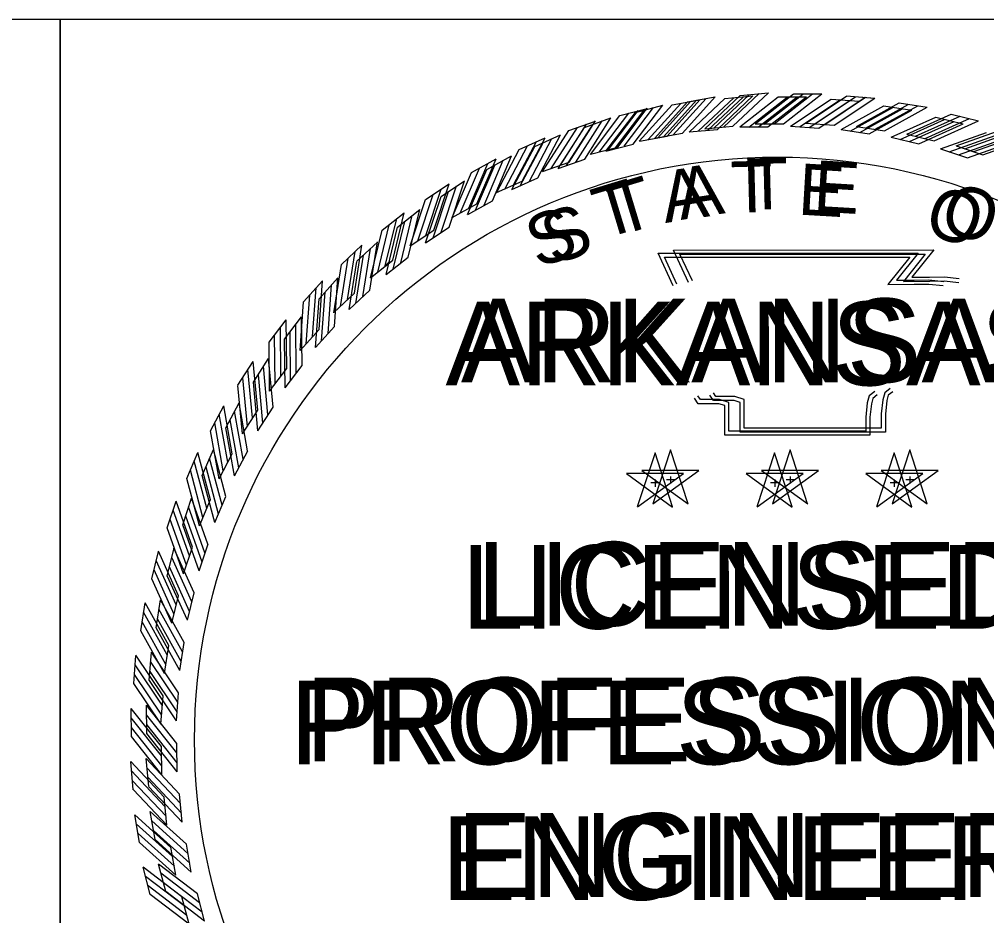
# Model space of a CAD drawing. Extents: x -2512 to 3792, y -435 to 2624.
# Drawn here: x 3002.5 to 3189.1, y 315.8 to 488.7 of the extents above; entities that cross this region are included whole.
import ezdxf

# ---------------------------------------------------------------- set-up
doc = ezdxf.new("R2010")
doc.units = 0
for name, color, linetype in [('1', 7, 'Continuous'), ('G-ANNO-NPLT', 7, 'Continuous'), ('R_No Plot', 7, 'Continuous'), ('STAMP', 7, 'Continuous'), ('STAMP_LKM', 7, 'Continuous')]:
    doc.layers.add(name, color=color, linetype=linetype)

msp = doc.modelspace()

# ---------------------------------------------------------------- linework, layer by layer
at = {"layer": '1'}
msp.add_line((3073.06, 441.09), (3073.99, 442.02), dxfattribs=at)
at = {"layer": 'G-ANNO-NPLT'}
msp.add_circle((3148.72, 349.66), 112.43, dxfattribs=at)
at = {"layer": 'R_No Plot'}
for points in [[(2730.1, 488.67), (3010.37, 488.67), (3010.37, 212.74), (2730.1, 212.74)], [(3010.37, 488.67), (3290.65, 488.67), (3290.65, 212.74), (3010.37, 212.74)]]:
    msp.add_lwpolyline(points, close=True, dxfattribs=at)
at = {"layer": 'STAMP'}
for p, q in [((3128.4, 472.17), (3133.75, 473.12)), ((3138.58, 473.39), (3144, 473.89)), ((3148.88, 473.69), (3154.32, 473.69)), ((3159.07, 473.28), (3164.5, 472.88)), ((3118.35, 470.12), (3123.61, 471.5)), ((3169.24, 471.96), (3174.62, 471.12)), ((3108.5, 467.24), (3113.63, 469.05)), ((3179.27, 469.81), (3184.56, 468.52)), ((3131.72, 466.94), (3137.15, 467.44)), ((3141.46, 467.9), (3146.91, 467.9)), ((3151.24, 468.05), (3156.68, 467.65)), ((3161.01, 467.4), (3166.4, 466.55)), ((3098.93, 463.56), (3103.89, 465.79)), ((3122.09, 465.18), (3127.46, 466.13)), ((3170.69, 465.94), (3175.99, 464.65)), ((3112.64, 462.63), (3117.91, 464.02)), ((3180.21, 463.68), (3185.39, 461.96)), ((3089.69, 459.1), (3094.45, 461.74)), ((3103.43, 459.31), (3108.57, 461.12)), ((3094.53, 455.24), (3099.51, 457.47)), ((3080.86, 453.9), (3085.38, 456.92)), ((3086, 450.44), (3090.77, 453.08)), ((3072.48, 447.98), (3076.74, 451.36)), ((3077.89, 444.96), (3082.43, 447.99)), ((3064.62, 441.39), (3068.59, 445.12)), ((3070.26, 438.83), (3074.53, 442.22)), ((3057.33, 434.18), (3060.98, 438.22)), ((3063.16, 432.09), (3067.14, 435.82)), ((3050.66, 426.39), (3053.96, 430.71)), ((3056.65, 424.79), (3060.3, 428.83)), ((3044.66, 418.07), (3047.59, 422.65)), ((3050.76, 416.97), (3054.07, 421.31)), ((3039.37, 409.29), (3041.91, 414.1)), ((3045.53, 408.7), (3048.47, 413.29)), ((3034.81, 400.1), (3036.95, 405.1)), ((3125.11, 405.04), (3121.7, 394.6)), ((3128.5, 394.61), (3125.11, 405.06)), ((3148.19, 405.04), (3144.78, 394.6)), ((3151.58, 394.61), (3148.19, 405.06)), ((3171.26, 405.04), (3167.86, 394.6)), ((3174.65, 394.61), (3171.27, 405.06)), ((3041.01, 400.02), (3043.56, 404.84)), ((3130.59, 401.06), (3119.61, 401.07)), ((3119.62, 401.06), (3128.5, 394.59)), ((3121.72, 394.61), (3130.61, 401.05)), ((3124.33, 399.3), (3125.96, 399.3)), ((3125.12, 399.89), (3125.12, 398.51)), ((3153.67, 401.06), (3142.69, 401.07)), ((3142.7, 401.06), (3151.58, 394.59)), ((3144.79, 394.61), (3153.69, 401.05)), ((3147.4, 399.3), (3149.04, 399.3)), ((3148.2, 399.89), (3148.2, 398.51)), ((3176.75, 401.06), (3165.77, 401.07)), ((3165.78, 401.06), (3174.66, 394.59)), ((3167.87, 394.61), (3176.76, 401.05)), ((3170.48, 399.3), (3172.11, 399.3)), ((3171.27, 399.89), (3171.27, 398.51)), ((3031.04, 390.56), (3032.76, 395.72)), ((3037.22, 390.99), (3039.36, 396.01)), ((3034.18, 381.69), (3035.91, 386.86)), ((3028.06, 380.75), (3029.35, 386.03)), ((3031.93, 372.16), (3033.22, 377.46)), ((3025.9, 370.72), (3026.75, 376.09)), ((3030.47, 362.48), (3031.32, 367.87)), ((3024.58, 360.55), (3024.98, 365.97)), ((3029.81, 352.72), (3030.21, 358.16)), ((3024.11, 350.3), (3024.06, 355.74)), ((3029.97, 342.93), (3029.92, 348.39)), ((3024.48, 340.05), (3023.98, 345.47)), ((3030.93, 333.19), (3030.43, 338.62)), ((3025.7, 329.87), (3024.75, 335.23)), ((3032.69, 323.56), (3031.74, 328.94)), ((3027.75, 319.82), (3026.37, 325.08)), ((3035.24, 314.12), (3033.85, 319.39))]:
    msp.add_line(p, q, dxfattribs=at)
for points in [[(3122.08, 465.17), (3128.39, 472.16)], [(3123.81, 465.46), (3130.12, 472.45)], [(3125.67, 465.83), (3131.97, 472.82)], [(3127.45, 466.13), (3133.76, 473.12)], [(3131.71, 466.93), (3138.57, 473.38)], [(3133.46, 467.08), (3140.32, 473.53)], [(3135.33, 467.29), (3142.2, 473.74)], [(3137.14, 467.44), (3144, 473.89)], [(3141.45, 467.9), (3148.87, 473.69)], [(3143.2, 467.88), (3150.63, 473.67)], [(3145.09, 467.92), (3152.52, 473.71)], [(3146.9, 467.9), (3154.33, 473.69)], [(3151.24, 468.05), (3159.07, 473.28)], [(3152.98, 467.9), (3160.81, 473.13)], [(3154.87, 467.81), (3162.7, 473.04)], [(3156.68, 467.66), (3164.5, 472.89)], [(3114.33, 463.05), (3120.04, 470.54)], [(3116.15, 463.57), (3121.86, 471.06)], [(3117.91, 464.02), (3123.61, 471.51)], [(3161, 467.39), (3169.24, 471.96)], [(3162.73, 467.1), (3170.96, 471.67)], [(3164.6, 466.85), (3172.84, 471.42)], [(3166.39, 466.55), (3174.62, 471.12)], [(3106.85, 460.54), (3111.92, 468.47)], [(3108.57, 461.13), (3113.64, 469.06)], [(3112.64, 462.62), (3118.34, 470.11)], [(3170.68, 465.93), (3179.26, 469.8)], [(3172.38, 465.5), (3180.96, 469.37)], [(3174.22, 465.1), (3182.81, 468.97)], [(3175.98, 464.65), (3184.56, 468.52)], [(3103.43, 459.3), (3108.5, 467.23)], [(3105.09, 459.87), (3110.15, 467.8)], [(3180.2, 463.68), (3189.08, 466.83)], [(3097.84, 456.75), (3102.24, 465.07)], [(3099.5, 457.47), (3103.9, 465.8)], [(3181.86, 463.11), (3190.73, 466.26)], [(3183.67, 462.55), (3192.54, 465.7)], [(3185.38, 461.96), (3194.25, 465.11)], [(3094.53, 455.23), (3098.93, 463.55)], [(3096.13, 455.93), (3100.53, 464.26)], [(3089.17, 452.22), (3092.86, 460.88)], [(3090.76, 453.08), (3094.46, 461.74)], [(3086, 450.44), (3089.69, 459.1)], [(3087.54, 451.27), (3091.23, 459.93)], [(3080.9, 447), (3083.87, 455.93)], [(3082.42, 447.99), (3085.39, 456.92)], [(3077.89, 444.96), (3080.85, 453.89)], [(3079.35, 445.91), (3082.32, 454.85)], [(3073.09, 441.11), (3075.31, 450.26)], [(3074.53, 442.22), (3076.74, 451.37)], [(3070.26, 438.82), (3072.48, 447.97)], [(3071.64, 439.9), (3073.86, 449.05)], [(3067.13, 435.82), (3068.59, 445.12)], [(3064.45, 433.27), (3065.91, 442.57)], [(3065.8, 434.59), (3067.26, 443.89)], [(3128.61, 437.28), (3125.71, 443.56), (3175.89, 443.59), (3171.7, 438.32), (3175.11, 438.36), (3177.95, 438.4), (3180.8, 438.09)], [(3129.33, 437.61), (3126.95, 442.76), (3174.24, 442.79), (3170.03, 437.5), (3175.12, 437.57), (3177.92, 437.6), (3180.71, 437.3)], [(3063.16, 432.08), (3064.62, 441.38)], [(3059.07, 427.5), (3059.75, 436.89)], [(3060.3, 428.83), (3060.98, 438.22)], [(3057.83, 426.07), (3058.51, 435.46)], [(3056.65, 424.78), (3057.33, 434.17)], [(3052.95, 419.87), (3052.85, 429.29)], [(3054.06, 421.3), (3053.96, 430.72)], [(3051.83, 418.35), (3051.74, 427.76)], [(3050.76, 416.96), (3050.66, 426.38)], [(3048.47, 413.29), (3047.59, 422.66)], [(3047.47, 411.77), (3046.6, 421.14)], [(3045.53, 408.69), (3044.66, 418.06)], [(3046.49, 410.15), (3045.62, 419.53)], [(3167.98, 416.25), (3167.13, 415.55), (3166.84, 414.51), (3166.56, 411.91), (3166.56, 408.44), (3138.55, 408.44), (3138.55, 413.12), (3138.55, 414.16), (3137.41, 414.51), (3133.43, 414.51), (3132.72, 415.59)], [(3167.48, 416.86), (3166.43, 416.01), (3166.06, 414.66), (3165.76, 411.95), (3165.76, 409.24), (3139.34, 409.24), (3139.34, 413.12), (3139.34, 414.75), (3137.53, 415.31), (3133.86, 415.31), (3133.38, 416.03)], [(3042.69, 403.24), (3041.05, 412.51)], [(3043.55, 404.83), (3041.91, 414.1)], [(3041.84, 401.55), (3040.2, 410.82)], [(3041.01, 400.01), (3039.37, 409.28)], [(3039.36, 396), (3036.95, 405.1)], [(3038.63, 394.34), (3036.22, 403.44)], [(3037.92, 392.59), (3035.52, 401.69)], [(3037.22, 390.98), (3034.82, 400.09)], [(3035.9, 386.86), (3032.75, 395.73)], [(3035.31, 385.14), (3032.17, 394.01)], [(3034.76, 383.34), (3031.61, 392.21)], [(3034.19, 381.68), (3031.04, 390.55)], [(3033.21, 377.46), (3029.34, 386.04)], [(3032.77, 375.7), (3028.9, 384.28)], [(3031.93, 372.16), (3028.06, 380.74)], [(3032.36, 373.85), (3028.49, 382.44)], [(3031.31, 367.87), (3026.75, 376.1)], [(3031.01, 366.08), (3026.45, 374.31)], [(3030.76, 364.2), (3026.2, 372.44)], [(3030.47, 362.48), (3025.91, 370.71)], [(3030.21, 358.15), (3024.98, 365.98)], [(3030.06, 356.35), (3024.83, 364.17)], [(3029.96, 354.46), (3024.73, 362.29)], [(3029.82, 352.71), (3024.59, 360.54)], [(3029.91, 348.38), (3024.05, 355.75)], [(3029.91, 346.57), (3024.05, 353.94)], [(3029.97, 344.68), (3024.11, 352.05)], [(3029.97, 342.93), (3024.11, 350.3)], [(3030.42, 338.62), (3023.98, 345.48)], [(3030.57, 336.81), (3024.13, 343.67)], [(3030.79, 334.93), (3024.34, 341.79)], [(3030.93, 333.19), (3024.49, 340.05)], [(3031.74, 328.93), (3024.75, 335.23)], [(3032.04, 327.14), (3025.05, 333.45)], [(3032.41, 325.29), (3025.41, 331.59)], [(3032.69, 323.56), (3025.7, 329.86)], [(3033.85, 319.38), (3026.36, 325.09)], [(3034.29, 317.63), (3026.81, 323.33)], [(3034.81, 315.81), (3027.33, 321.51)], [(3035.24, 314.11), (3027.76, 319.82)]]:
    msp.add_lwpolyline(points, dxfattribs=at)
at = {"layer": 'STAMP_LKM'}
for p, q in [((3141.56, 473.98), (3146.98, 474.48)), ((3151.86, 474.28), (3157.3, 474.28)), ((3121.33, 470.71), (3126.59, 472.1)), ((3131.37, 472.76), (3136.73, 473.71)), ((3162.05, 473.88), (3167.47, 473.48)), ((3162.05, 473.88), (3167.48, 473.48)), ((3172.22, 472.56), (3177.6, 471.71)), ((3182.25, 470.4), (3187.54, 469.11)), ((3111.48, 467.83), (3116.61, 469.65)), ((3144.44, 468.5), (3149.89, 468.5)), ((3154.22, 468.65), (3159.66, 468.25)), ((3154.22, 468.65), (3159.66, 468.25)), ((3125.07, 465.77), (3130.44, 466.72)), ((3134.7, 467.53), (3140.13, 468.04)), ((3163.99, 467.99), (3169.37, 467.14)), ((3173.67, 466.53), (3178.96, 465.24)), ((3101.91, 464.16), (3106.87, 466.39)), ((3115.62, 463.22), (3120.89, 464.61)), ((3183.19, 464.28), (3188.36, 462.55)), ((3092.67, 459.7), (3097.43, 462.33)), ((3106.41, 459.9), (3111.55, 461.72)), ((3083.83, 454.49), (3088.36, 457.51)), ((3097.51, 455.83), (3102.48, 458.07)), ((3088.98, 451.04), (3093.75, 453.68)), ((3075.46, 448.58), (3079.72, 451.96)), ((3080.87, 445.56), (3085.4, 448.58)), ((3067.6, 441.99), (3071.57, 445.71)), ((3073.24, 439.43), (3077.51, 442.82)), ((3060.31, 434.77), (3063.96, 438.81)), ((3066.14, 432.69), (3070.12, 436.42)), ((3053.64, 426.98), (3056.94, 431.31)), ((3059.63, 425.38), (3063.28, 429.43)), ((3047.64, 418.66), (3050.57, 423.25)), ((3053.74, 417.57), (3057.04, 421.9)), ((3042.34, 409.88), (3044.89, 414.69)), ((3048.51, 409.29), (3051.45, 413.88)), ((3037.79, 400.69), (3039.93, 405.69)), ((3043.99, 400.61), (3046.54, 405.43)), ((3128.08, 405.64), (3124.68, 395.19)), ((3131.48, 395.2), (3128.09, 405.65)), ((3151.16, 405.64), (3147.76, 395.19)), ((3154.55, 395.2), (3151.17, 405.65)), ((3174.24, 405.64), (3170.84, 395.19)), ((3177.63, 395.2), (3174.25, 405.65)), ((3133.57, 401.65), (3122.59, 401.66)), ((3122.6, 401.65), (3131.48, 395.19)), ((3124.69, 395.2), (3133.59, 401.65)), ((3156.65, 401.65), (3145.67, 401.66)), ((3145.68, 401.65), (3154.56, 395.19)), ((3147.77, 395.2), (3156.66, 401.65)), ((3179.73, 401.65), (3168.74, 401.66)), ((3168.75, 401.65), (3177.63, 395.19)), ((3170.85, 395.2), (3179.74, 401.65)), ((3127.3, 399.9), (3128.94, 399.9)), ((3128.1, 400.48), (3128.1, 399.1)), ((3150.38, 399.9), (3152.01, 399.9)), ((3151.17, 400.48), (3151.17, 399.1)), ((3173.46, 399.9), (3175.09, 399.9)), ((3174.25, 400.48), (3174.25, 399.1)), ((3034.02, 391.16), (3035.73, 396.32)), ((3040.2, 391.59), (3042.34, 396.6)), ((3031.04, 381.34), (3032.33, 386.63)), ((3037.16, 382.28), (3038.89, 387.46)), ((3034.91, 372.76), (3036.2, 378.06)), ((3028.88, 371.31), (3029.73, 376.69)), ((3033.45, 363.08), (3034.3, 368.47)), ((3027.56, 361.14), (3027.96, 366.57)), ((3032.79, 353.31), (3033.19, 358.75)), ((3027.09, 350.9), (3027.04, 356.34)), ((3032.94, 343.53), (3032.89, 348.98)), ((3027.46, 340.65), (3026.96, 346.07)), ((3033.9, 333.79), (3033.4, 339.22)), ((3028.67, 330.47), (3027.73, 335.82)), ((3035.67, 324.16), (3034.72, 329.53)), ((3030.73, 320.42), (3029.34, 325.68)), ((3038.22, 314.71), (3036.83, 319.98))]:
    msp.add_line(p, q, dxfattribs=at)
for points in [[(3134.69, 467.53), (3141.55, 473.98)], [(3136.43, 467.67), (3143.3, 474.12)], [(3138.31, 467.89), (3145.17, 474.33)], [(3140.12, 468.04), (3146.98, 474.48)], [(3144.43, 468.49), (3151.85, 474.28)], [(3146.18, 468.47), (3153.6, 474.26)], [(3148.07, 468.52), (3155.49, 474.31)], [(3149.88, 468.5), (3157.31, 474.29)], [(3120.88, 464.61), (3126.59, 472.1)], [(3125.06, 465.77), (3131.37, 472.76)], [(3126.79, 466.06), (3133.09, 473.05)], [(3128.64, 466.42), (3134.95, 473.42)], [(3130.43, 466.72), (3136.74, 473.71)], [(3154.21, 468.64), (3162.04, 473.87)], [(3154.21, 468.64), (3162.04, 473.87)], [(3155.96, 468.5), (3163.79, 473.73)], [(3155.96, 468.5), (3163.79, 473.73)], [(3157.85, 468.4), (3165.67, 473.63)], [(3157.85, 468.4), (3165.68, 473.63)], [(3159.65, 468.25), (3167.48, 473.48)], [(3159.65, 468.25), (3167.48, 473.48)], [(3163.98, 467.99), (3172.21, 472.55)], [(3165.71, 467.7), (3173.94, 472.26)], [(3115.61, 463.22), (3121.32, 470.7)], [(3117.31, 463.65), (3123.02, 471.13)], [(3119.13, 464.17), (3124.83, 471.66)], [(3167.58, 467.45), (3175.81, 472.01)], [(3169.37, 467.15), (3177.6, 471.71)], [(3173.66, 466.53), (3182.24, 470.4)], [(3108.06, 460.46), (3113.13, 468.4)], [(3109.83, 461.13), (3114.9, 469.07)], [(3111.55, 461.72), (3116.61, 469.65)], [(3175.36, 466.1), (3183.94, 469.97)], [(3177.2, 465.69), (3185.78, 469.56)], [(3178.96, 465.25), (3187.54, 469.12)], [(3106.41, 459.89), (3111.48, 467.83)], [(3183.18, 464.27), (3192.05, 467.42)], [(3184.84, 463.71), (3193.71, 466.85)], [(3099.11, 456.53), (3103.51, 464.85)], [(3100.82, 457.34), (3105.21, 465.66)], [(3102.48, 458.07), (3106.87, 466.39)], [(3186.64, 463.15), (3195.52, 466.3)], [(3188.36, 462.56), (3197.23, 465.71)], [(3097.51, 455.82), (3101.9, 464.15)], [(3092.15, 452.82), (3095.84, 461.47)], [(3093.74, 453.68), (3097.43, 462.34)], [(3088.97, 451.03), (3092.67, 459.69)], [(3090.51, 451.86), (3094.21, 460.52)], [(3085.4, 448.58), (3088.36, 457.52)], [(3082.33, 446.51), (3085.3, 455.44)], [(3083.88, 447.59), (3086.85, 456.53)], [(3080.86, 445.55), (3083.83, 454.48)], [(3077.5, 442.81), (3079.72, 451.96)], [(3076.07, 441.7), (3078.29, 450.85)], [(3073.24, 439.42), (3075.45, 448.57)], [(3074.62, 440.49), (3076.84, 449.64)], [(3068.78, 435.19), (3070.23, 444.49)], [(3070.11, 436.42), (3071.57, 445.72)], [(3131.59, 437.87), (3128.69, 444.15), (3178.87, 444.18), (3174.68, 438.91), (3178.08, 438.96), (3180.93, 438.99), (3183.78, 438.68)], [(3067.43, 433.86), (3068.88, 443.17)], [(3132.31, 438.2), (3129.93, 443.36), (3177.22, 443.38), (3173.01, 438.1), (3178.09, 438.16), (3180.89, 438.2), (3183.69, 437.89)], [(3066.14, 432.68), (3067.59, 441.98)], [(3063.27, 429.43), (3063.96, 438.82)], [(3062.05, 428.09), (3062.73, 437.48)], [(3059.62, 425.37), (3060.31, 434.76)], [(3060.81, 426.66), (3061.49, 436.05)], [(3057.04, 421.9), (3056.94, 431.31)], [(3055.92, 420.47), (3055.83, 429.88)], [(3054.81, 418.94), (3054.71, 428.35)], [(3053.74, 417.56), (3053.64, 426.97)], [(3050.45, 412.36), (3049.58, 421.74)], [(3051.44, 413.88), (3050.57, 423.25)], [(3049.47, 410.75), (3048.6, 420.12)], [(3048.51, 409.28), (3047.64, 418.66)], [(3170.96, 416.84), (3170.11, 416.15), (3169.82, 415.11), (3169.54, 412.5), (3169.54, 409.04), (3141.53, 409.04), (3141.53, 413.72), (3141.53, 414.76), (3140.39, 415.11), (3136.41, 415.11), (3135.7, 416.19)], [(3170.46, 417.46), (3169.41, 416.6), (3169.04, 415.25), (3168.74, 412.55), (3168.74, 409.83), (3142.32, 409.83), (3142.32, 413.72), (3142.32, 415.35), (3140.51, 415.9), (3136.83, 415.9), (3136.36, 416.62)], [(3046.53, 405.43), (3044.89, 414.7)], [(3045.67, 403.83), (3044.02, 413.1)], [(3044.82, 402.14), (3043.18, 411.41)], [(3043.99, 400.6), (3042.34, 409.87)], [(3042.33, 396.6), (3039.93, 405.7)], [(3041.61, 394.94), (3039.2, 404.04)], [(3040.9, 393.18), (3038.5, 402.29)], [(3040.2, 391.58), (3037.79, 400.68)], [(3038.88, 387.45), (3035.73, 396.32)], [(3038.29, 385.74), (3035.14, 394.61)], [(3037.73, 383.93), (3034.59, 392.8)], [(3037.16, 382.27), (3034.02, 391.15)], [(3036.19, 378.05), (3032.32, 386.63)], [(3035.75, 376.29), (3031.88, 384.88)], [(3035.34, 374.45), (3031.47, 383.03)], [(3034.91, 372.75), (3031.04, 381.33)], [(3034.29, 368.46), (3029.73, 376.69)], [(3033.99, 366.67), (3029.43, 374.91)], [(3033.45, 363.07), (3028.89, 371.31)], [(3033.74, 364.8), (3029.17, 373.03)], [(3033.19, 358.75), (3027.96, 366.57)], [(3033.04, 356.94), (3027.81, 364.77)], [(3032.94, 355.05), (3027.71, 362.88)], [(3032.8, 353.31), (3027.57, 361.14)], [(3032.89, 348.97), (3027.03, 356.34)], [(3032.89, 347.16), (3027.03, 354.53)], [(3032.95, 345.27), (3027.09, 352.64)], [(3032.95, 343.52), (3027.09, 350.89)], [(3033.4, 339.21), (3026.95, 346.07)], [(3033.55, 337.4), (3027.1, 344.27)], [(3033.77, 335.53), (3027.32, 342.39)], [(3033.91, 333.78), (3027.46, 340.64)], [(3034.72, 329.52), (3027.72, 335.83)], [(3035.01, 327.74), (3028.02, 334.04)], [(3035.38, 325.88), (3028.39, 332.19)], [(3035.67, 324.15), (3028.68, 330.46)], [(3036.83, 319.98), (3029.34, 325.68)], [(3037.27, 318.22), (3029.78, 323.93)], [(3037.79, 316.4), (3030.3, 322.11)], [(3038.22, 314.71), (3030.73, 320.41)]]:
    msp.add_lwpolyline(points, dxfattribs=at)

# ---------------------------------------------------------------- texts
at = {"layer": 'STAMP'}
for s, rotation, p in [('T', 1.4789, (3139.86, 451.33)), ('A', 8.6788, (3127.08, 449.36)), ('E', 356.672, (3152.53, 451.02)), ('T', 16.9015, (3115.06, 446.22)), ('O', 341.2218, (3176.56, 447.63)), ('S', 19.7726, (3102.48, 440.57))]:
    msp.add_text(s, height=9.9, rotation=rotation, dxfattribs=at).set_placement(p)
for s, height, p in [('ARKANSAS', 16.155, (3084.69, 418.05)), ('LICENSED', 16.155, (3087.77, 371.1)), ('PROFESSIONAL', 16.1547, (3054.69, 344.94)), ('ENGINEER', 16.155, (3083.92, 318.79))]:
    msp.add_text(s, height=height, dxfattribs=at).set_placement(p)
at = {"layer": 'STAMP_LKM'}
for s, rotation, p in [('T', 1.4789, (3142.84, 451.92)), ('T', 1.4789, (3142.84, 451.92)), ('E', 356.672, (3155.51, 451.62)), ('A', 8.6788, (3130.06, 449.95)), ('T', 16.9015, (3118.04, 446.81)), ('O', 341.2218, (3179.54, 448.22)), ('S', 19.7726, (3105.46, 441.16))]:
    msp.add_text(s, height=9.9, rotation=rotation, dxfattribs=at).set_placement(p)
for s, height, p in [('ARKANSAS', 16.155, (3087.67, 418.65)), ('LICENSED', 16.155, (3090.75, 371.69)), ('PROFESSIONAL', 16.1547, (3057.67, 345.54)), ('ENGINEER', 16.155, (3086.9, 319.38))]:
    msp.add_text(s, height=height, dxfattribs=at).set_placement(p)

doc.saveas('drawing.dxf')
